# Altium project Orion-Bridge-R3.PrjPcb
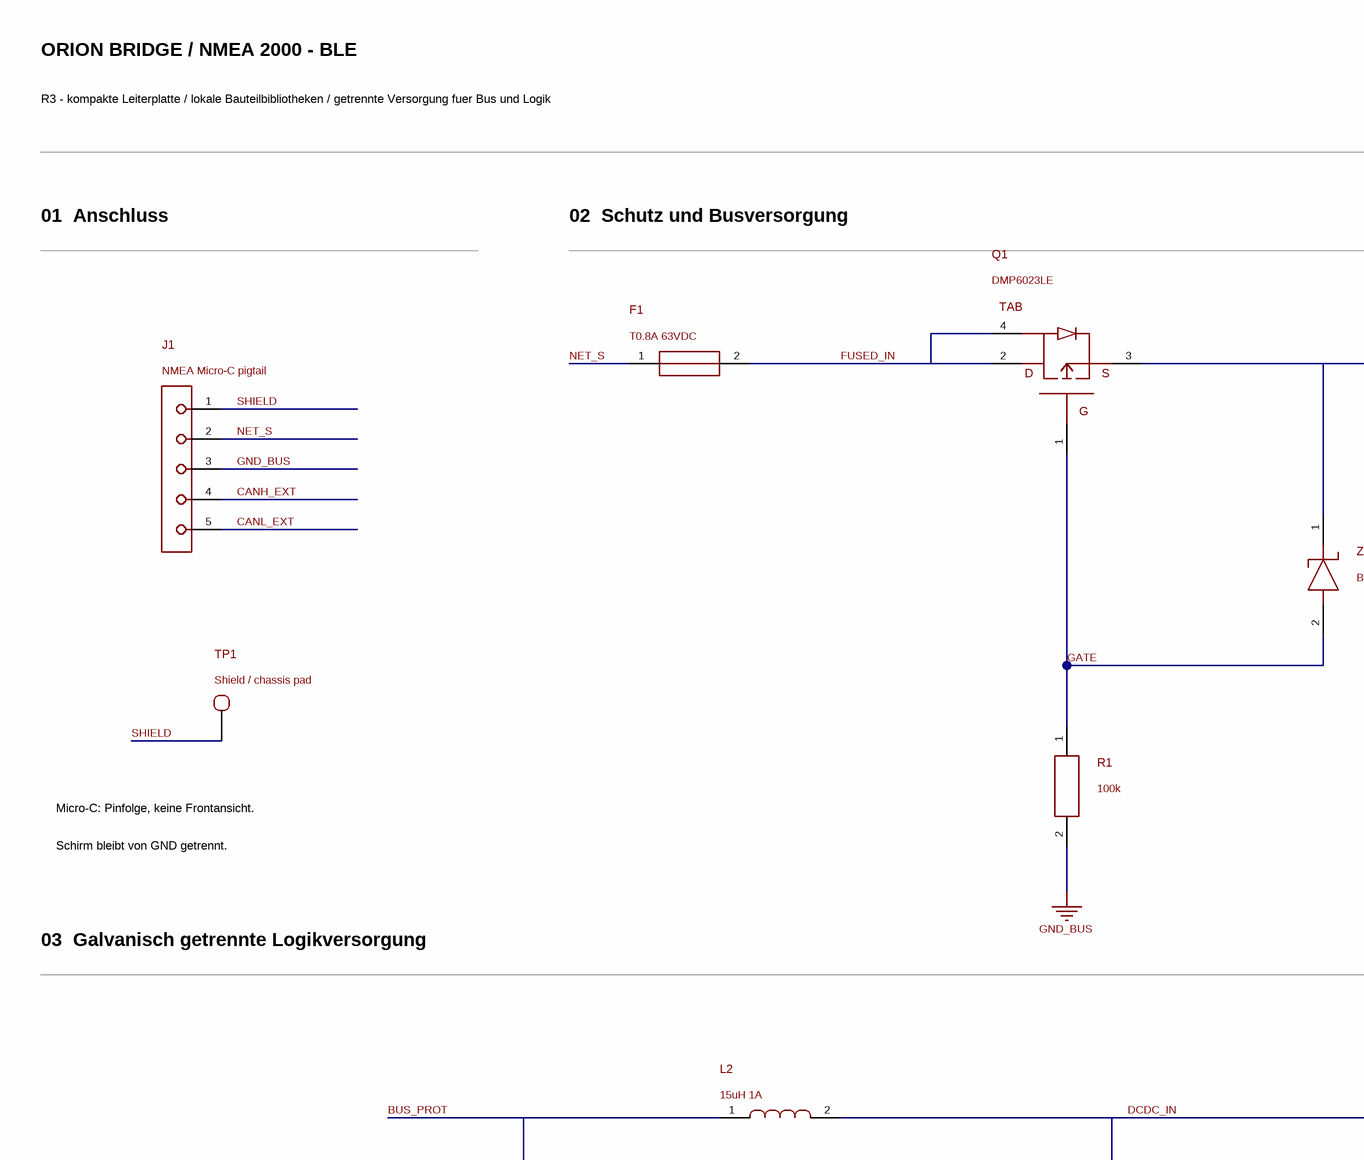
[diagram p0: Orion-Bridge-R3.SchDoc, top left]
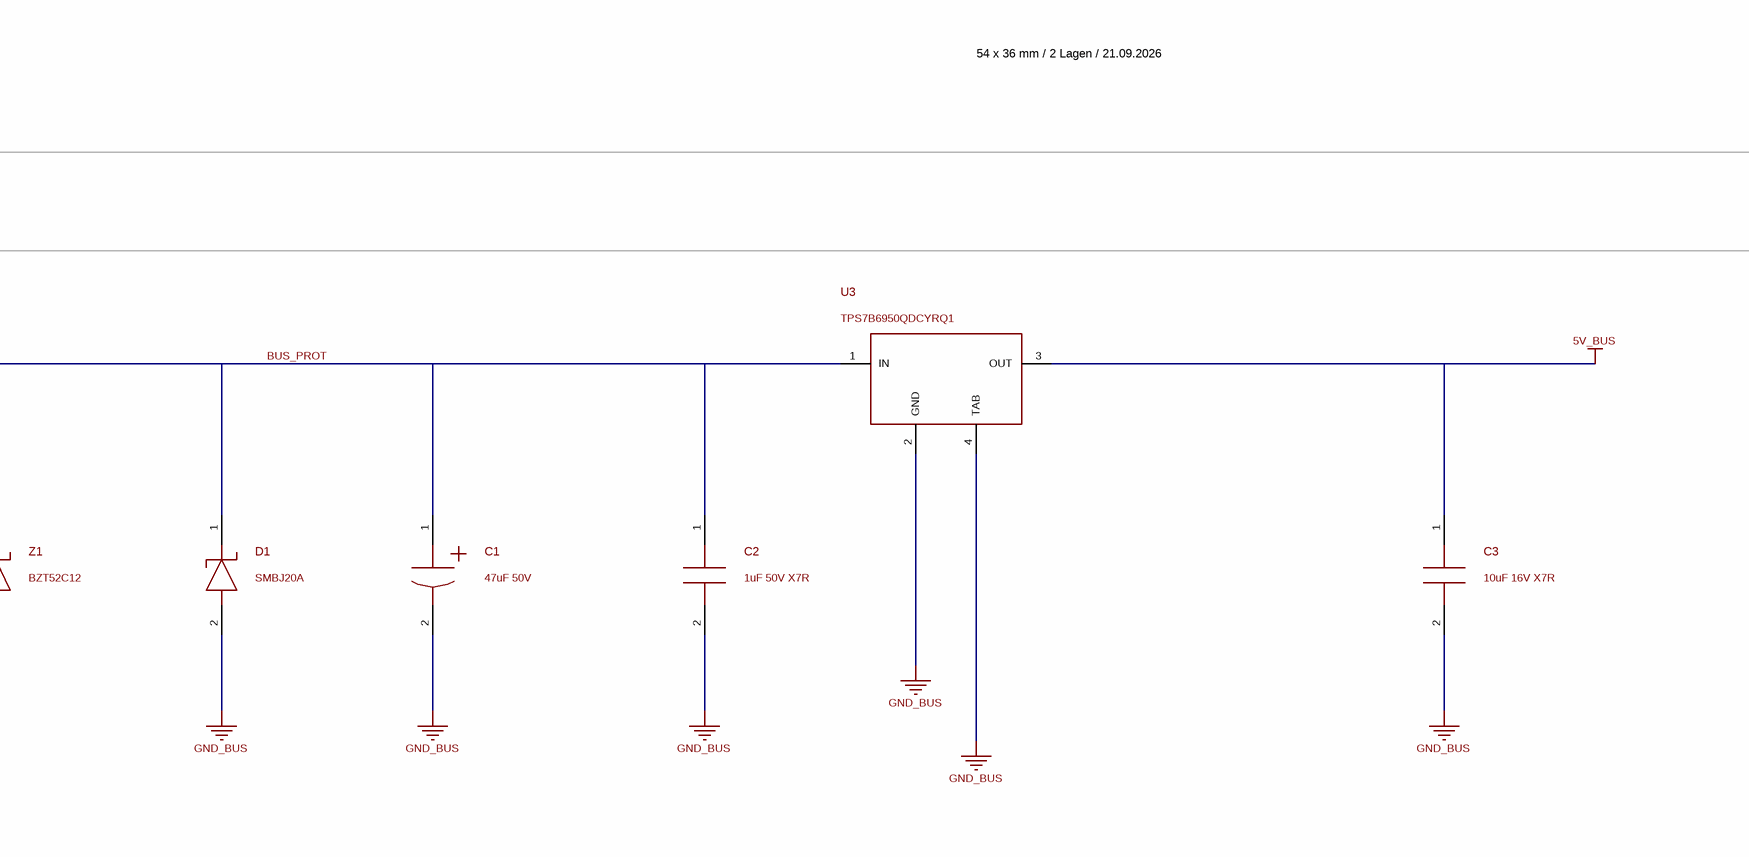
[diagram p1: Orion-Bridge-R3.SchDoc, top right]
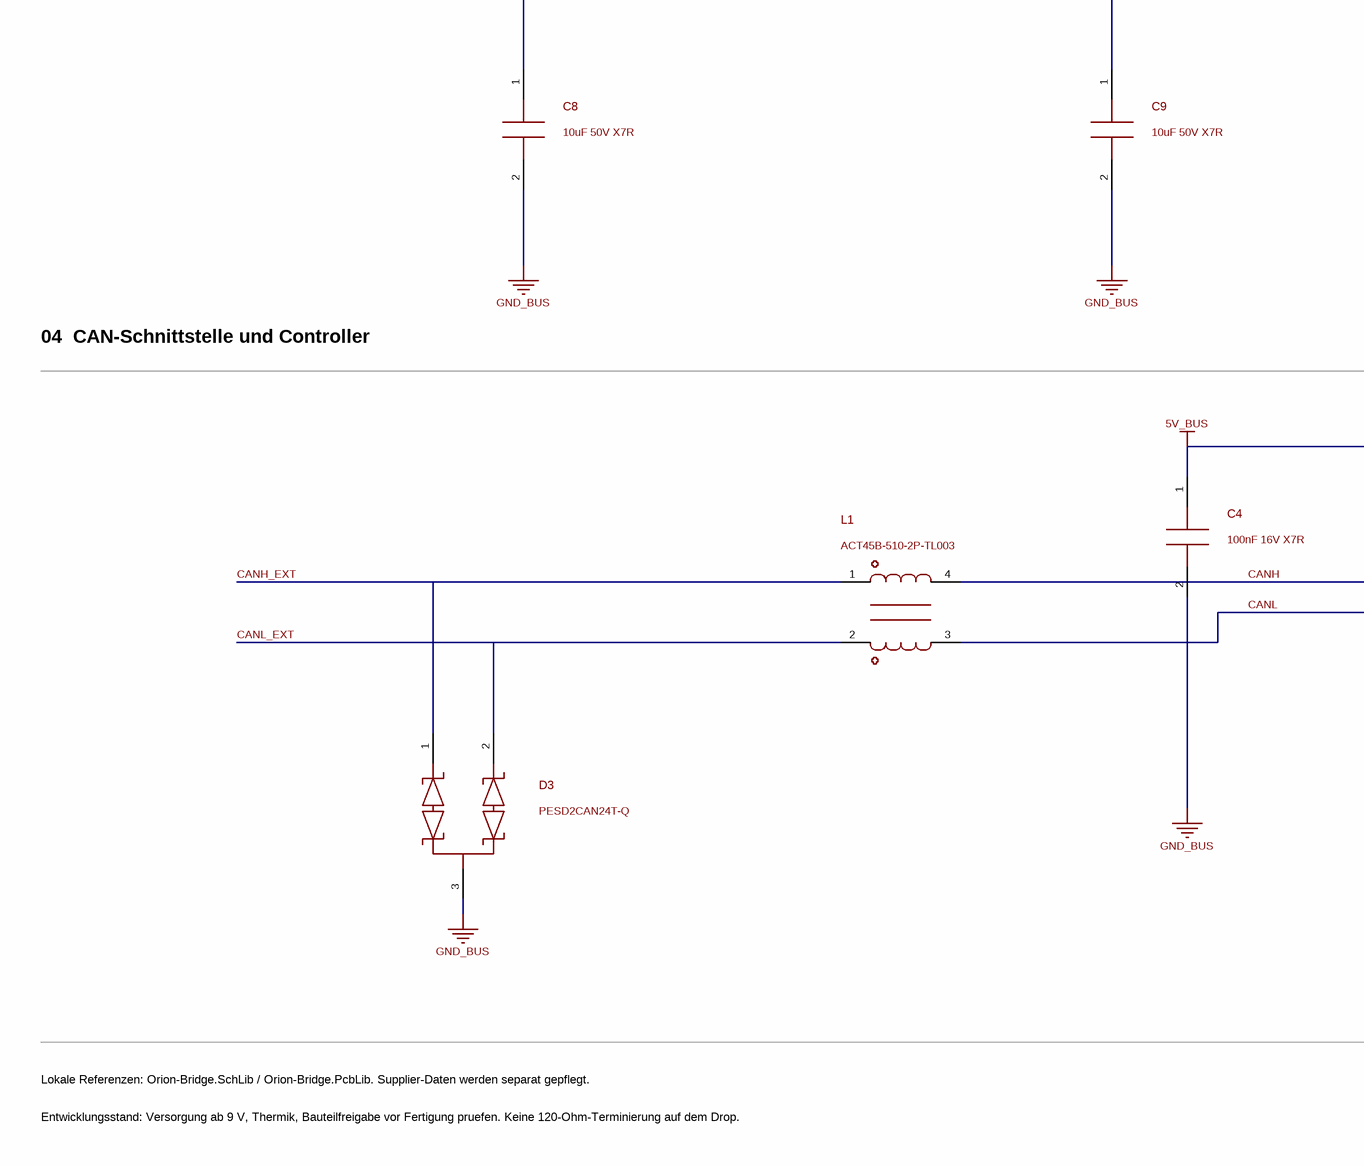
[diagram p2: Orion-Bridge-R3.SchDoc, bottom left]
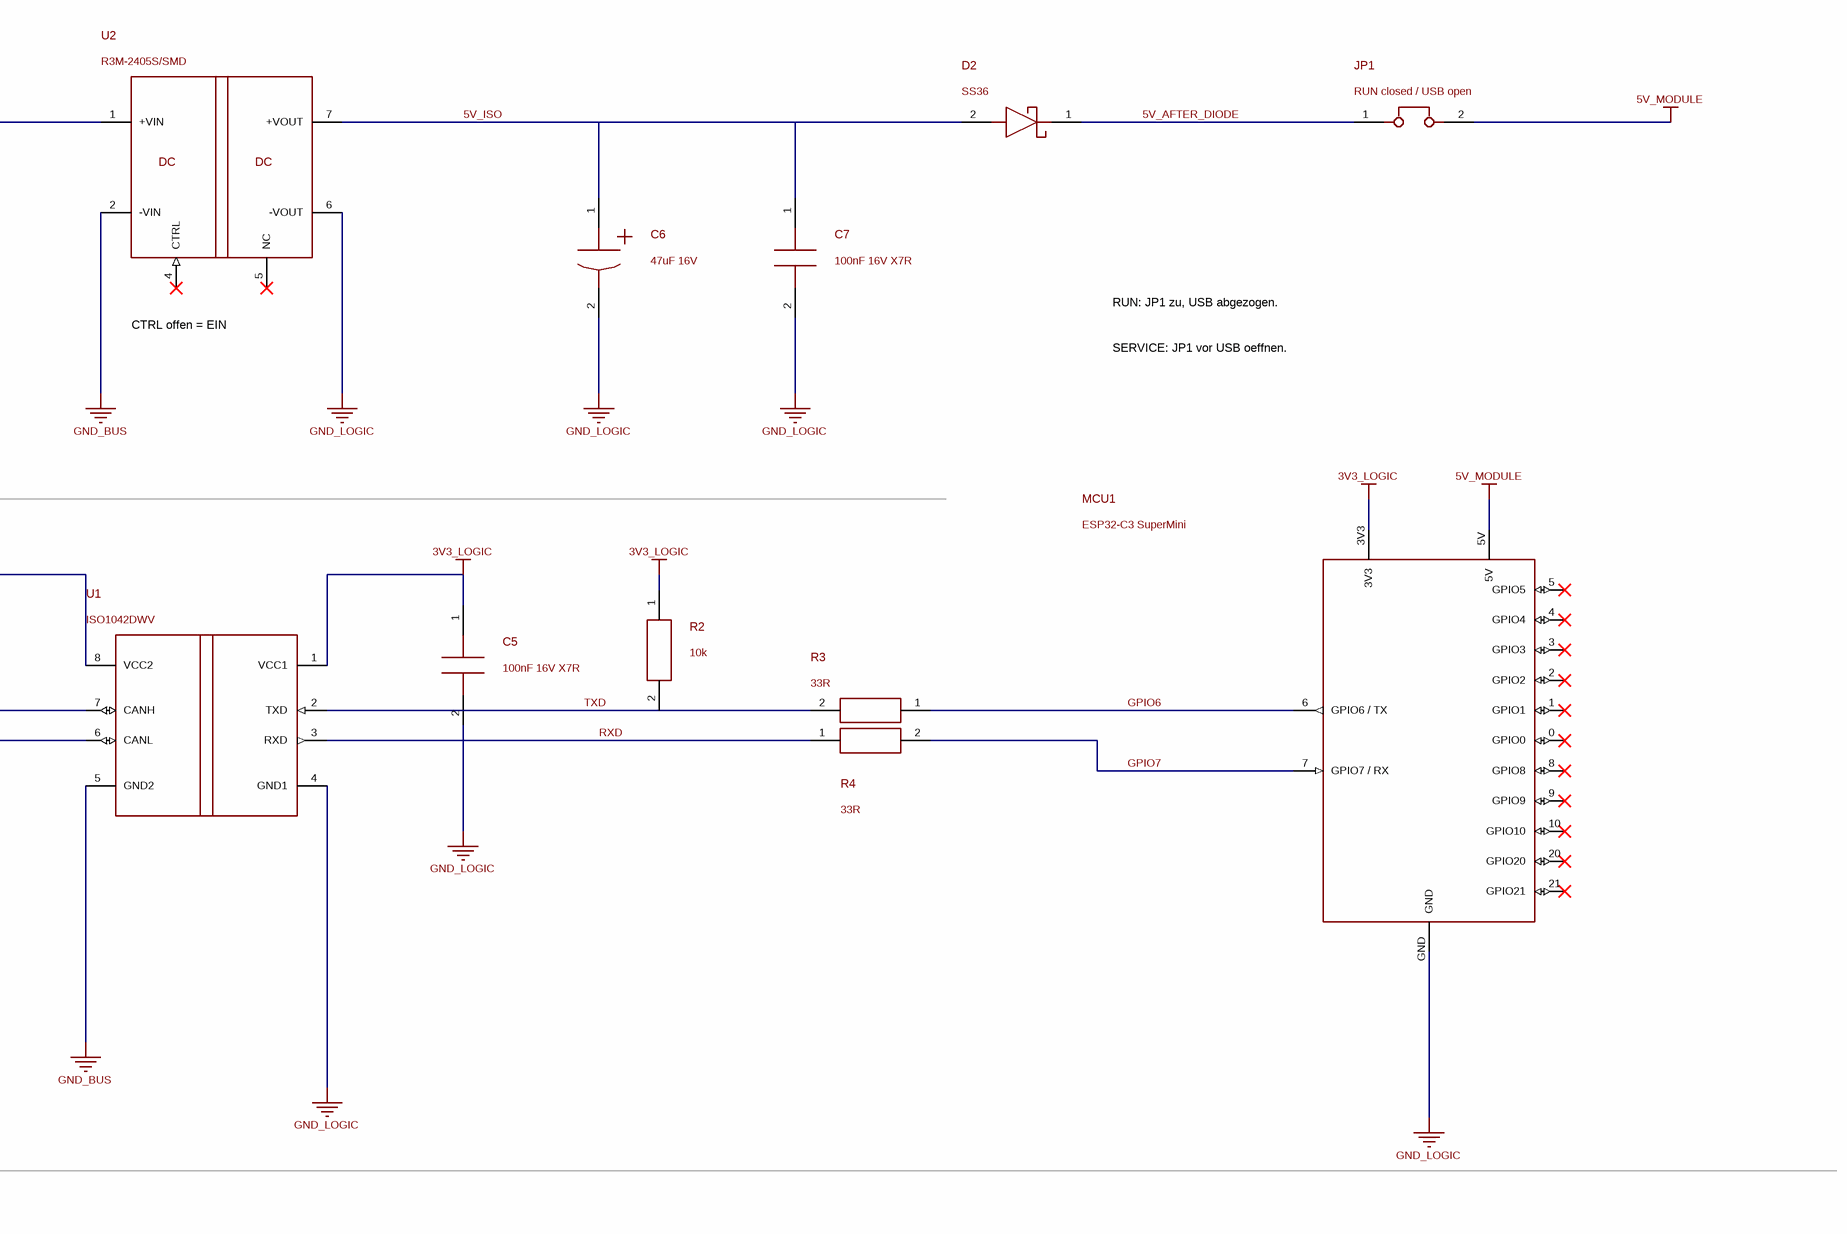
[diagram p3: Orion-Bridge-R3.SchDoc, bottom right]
1 sheet, 28 parts. Net scope: global (net labels, ports and power ports of the same name join across sheets).
Board file: Orion-Bridge-R3.PcbDoc

## Sheet Orion-Bridge-R3.SchDoc
size A2

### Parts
C1  47uF 50V  [PANASONIC_FT_D6P3]
C2  1uF 50V X7R  [C0805]
C3  10uF 16V X7R  [C1206]
C4  100nF 16V X7R  [C0805]
C5  100nF 16V X7R  [C0805]
C6  47uF 16V  [PANASONIC_FT_D4]
C7  100nF 16V X7R  [C0805]
C8  10uF 50V X7R  [C1210]
C9  10uF 50V X7R  [C1210]
D1  SMBJ20A  [SMB]
D2  SS36  [SMB]
D3  PESD2CAN24T-Q  [SOT23_NEXPERIA_REFLOW]
F1  T0.8A 63VDC  [BOURNS_SF1206S]
J1  NMEA Micro-C pigtail  [PIGTAIL_5_P3_D1P3]
JP1  RUN closed / USB open  [HDR1X2_2.54]
L1  ACT45B-510-2P-TL003  [ACT45B]
L2  15uH 1A  [BOURNS_SRN4018]
MCU1  ESP32-C3 SuperMini  [NOLOGO_C3_SUPERMINI_THT_2X8]
Q1  DMP6023LE  [SOT223_DIODES_DMP6023LE]
R1  100k  [R0805]
R2  10k  [R0805]
R3  33R  [R0805]
R4  33R  [R0805]
TP1  Shield / chassis pad  [TESTPOINT_2MM]
U1  ISO1042DWV  [SOIC8_DWV]
U2  R3M-2405S/SMD  [R3M_SMD]
U3  TPS7B6950QDCYRQ1  [SOT223_LDO]
Z1  BZT52C12  [SOD123]

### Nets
3V3_LOGIC: C5.1 MCU1.3V3 R2.1 U1.1(VCC1)
5V_BUS: C3.1 C4.1 U1.8(VCC2) U3.3(OUT)
5V_MODULE: JP1.2 MCU1.5V
GND_BUS: C1.2(-) C2.2 C3.2 C4.2 C8.2 C9.2 D1.2(A) D3.3(CC) J1.3(NET-C) R1.2 U1.5(GND2) U2.2(-VIN) U3.2(GND) U3.4(TAB)
GND_LOGIC: C5.2 C6.2(-) C7.2 MCU1.GND U1.4(GND1) U2.6(-VOUT)
5V_AFTER_DIODE: D2.1(K) JP1.1
5V_ISO: C6.1(+) C7.1 D2.2(A) U2.7(+VOUT)
BUS_PROT: C1.1(+) C2.1 C8.1 D1.1(K) L2.1 Q1.3(S) U3.1(IN) Z1.1(K)
CANH: L1.4(H_IC) U1.7(CANH)
CANH_EXT: D3.1(K1) J1.4(CAN-H) L1.1(H_EXT)
CANL: L1.3(L_IC) U1.6(CANL)
CANL_EXT: D3.2(K2) J1.5(CAN-L) L1.2(L_EXT)
DCDC_IN: C9.1 L2.2 U2.1(+VIN)
FUSED_IN: F1.2 Q1.2(D) Q1.4(TAB=D)
GATE: Q1.1(G) R1.1 Z1.2(A)
GPIO6: MCU1.6(GPIO6_/_TX) R3.1
GPIO7: MCU1.7(GPIO7_/_RX) R4.2
NET_S: F1.1 J1.2(NET-S)
RXD: R4.1 U1.3(RXD)
SHIELD: J1.1(SHIELD) TP1.1(SHIELD)
TXD: R2.2 R3.2 U1.2(TXD)

Not connected (* = marked no-connect by the designer): MCU1 0(GPIO0)* 1(GPIO1)* 2(GPIO2)* 3(GPIO3)* 4(GPIO4)* 5(GPIO5)* 8(GPIO8)* 9(GPIO9)* 10(GPIO10)* 20(GPIO20)* 21(GPIO21)*; U2 4(CTRL)* 5(NC)*

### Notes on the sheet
- ORION BRIDGE / NMEA 2000 - BLE
- 54 x 36 mm / 2 Lagen / 21.09.2026
- R3 - kompakte Leiterplatte / lokale Bauteilbibliotheken / getrennte Versorgung fuer Bus und Logik
- 01  Anschluss
- 02  Schutz und Busversorgung
- Micro-C: Pinfolge, keine Frontansicht.
- Schirm bleibt von GND getrennt.
- 03  Galvanisch getrennte Logikversorgung
- CTRL offen = EIN
- RUN: JP1 zu, USB abgezogen.
- SERVICE: JP1 vor USB oeffnen.
- 04  CAN-Schnittstelle und Controller
- Lokale Referenzen: Orion-Bridge.SchLib / Orion-Bridge.PcbLib. Supplier-Daten werden separat gepflegt.
- Entwicklungsstand: Versorgung ab 9 V, Thermik, Bauteilfreigabe vor Fertigung pruefen. Keine 120-Ohm-Terminierung auf dem Drop.

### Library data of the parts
C1 = CAP_PANASONIC_EEEFT1H470AP: 47 uF 50 V FT-series SMD aluminum electrolytic, size D, standard product; Manufacturer: Panasonic Industry; ReviewStatus: Manufacturer recommended lands verified from primary datasheet; assembly/electrical qualification remains
C2 = C_0805_1UF_50V_X7R: 1uF 50V X7R - generic specification; manufacturer/MPN not selected; ReviewStatus: PROVISIONAL - verify landpattern before fabrication
C3 = C_1206_10UF_16V_X7R: 10uF 16V X7R - generic specification; manufacturer/MPN not selected; ReviewStatus: PROVISIONAL - verify landpattern before fabrication
C4 C5 C7 = C_0805_100NF_16V_X7R: 100nF 16V X7R - generic specification; manufacturer/MPN not selected; ReviewStatus: PROVISIONAL - verify landpattern before fabrication
C6 = CAP_PANASONIC_EEEFT1C470AR: 47 uF 16 V FT-series SMD aluminum electrolytic, size B, standard product; Manufacturer: Panasonic Industry; ReviewStatus: Manufacturer recommended lands verified from primary datasheet; assembly/electrical qualification remains
C8 C9 = C_1210_10UF_50V_X7R: 10uF 50V X7R - generic specification; manufacturer/MPN not selected; ReviewStatus: PROVISIONAL - verify landpattern before fabrication
D1 = SMBJ20A_SMB_GENERIC: SMBJ20A - generic specification; manufacturer/MPN not selected; ReviewStatus: PROVISIONAL - verify landpattern before fabrication
D2 = SS36_SMB_GENERIC: SS36 - generic specification; manufacturer/MPN not selected; ReviewStatus: PROVISIONAL - verify landpattern before fabrication
D3 = PESD2CAN24T-QR: Manufacturer: Nexperia; ReviewStatus: Nexperia PESD2CAN24T-Q datasheet Fig10 reflow lands, 9-Feb-2024 p8
F1 = FUSE_BOURNS_SF1206S080: 0.8 A slow-blow SMD ceramic fuse, 63 VDC, 50 A interrupt rating; Manufacturer: Bourns; MPN: SF-1206S080-2; ReviewStatus: Manufacturer recommended lands verified from primary datasheet; assembly/electrical qualification remains
J1 = NMEA_PIGTAIL_5_P3_D1P3: Five direct wire-solder pads for a separately selected Micro-C cable; this is a PCB interface, not an invented connector MPN or face view; ReviewStatus: Designed wire interface; cable conductor and strain relief selection pending
JP1 = JUMPER_1X2_P2_54: RUN closed / USB open - generic specification; manufacturer/MPN not selected; ReviewStatus: PROVISIONAL - verify landpattern before fabrication
L1 = ACT45B5102PTL003: Manufacturer: TDK; ReviewStatus: PROVISIONAL - verify landpattern before fabrication
L2 = IND_BOURNS_SRN4018_150M: 15 uH semi-shielded power inductor, 1.0 A RMS and 1.1 A saturation rating; Manufacturer: Bourns; MPN: SRN4018-150M; ReviewStatus: Manufacturer recommended lands verified from primary datasheet; assembly/electrical qualification remains
MCU1 = ESP32_C3_SUPERMINI_NOLOGO: Nologo ESP32-C3 SuperMini module, two 1x8 carrier headers, GPIO6 TX / GPIO7 RX; Manufacturer: Nologo Tech; ReviewStatus: Nologo source-based header pin geometry. Local model assumes 3.1 mm underside clearance and 7.2 mm total height; no separate socket part is specified.
Q1 = DMP6023LE: Manufacturer: Diodes Incorporated; ReviewStatus: Diodes manufacturer suggested land pattern, DS37199 Rev.3-2 p6
R1 = R_0805_100K: 100k - generic specification; manufacturer/MPN not selected; ReviewStatus: PROVISIONAL - verify landpattern before fabrication
R2 = R_0805_10K: 10k - generic specification; manufacturer/MPN not selected; ReviewStatus: PROVISIONAL - verify landpattern before fabrication
R3 = R_0805_33R: 33R - generic specification; manufacturer/MPN not selected; Role: R_TX; ReviewStatus: PROVISIONAL - verify landpattern before fabrication
R4 = R_0805_33R: 33R - generic specification; manufacturer/MPN not selected; Role: R_RX; ReviewStatus: PROVISIONAL - verify landpattern before fabrication
TP1 = TESTPOINT_2MM: Shield / chassis pad - generic specification; manufacturer/MPN not selected; ReviewStatus: PROVISIONAL - verify landpattern before fabrication
U1 = ISO1042DWV: Manufacturer: Texas Instruments; ReviewStatus: PROVISIONAL - verify landpattern before fabrication
U2 = R3M-2405S_SMD: Manufacturer: RECOM; ReviewStatus: PROVISIONAL - verify landpattern before fabrication
U3 = TPS7B6950QDCYRQ1: Manufacturer: Texas Instruments; ReviewStatus: TI DCY mechanical envelope verified; R2 engineering lands retained, not manufacturer-recommended lands. Thermal/assembly qualification required.
Z1 = BZT52C12_SOD123_GENERIC: BZT52C12 - generic specification; manufacturer/MPN not selected; ReviewStatus: PROVISIONAL - verify landpattern before fabrication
